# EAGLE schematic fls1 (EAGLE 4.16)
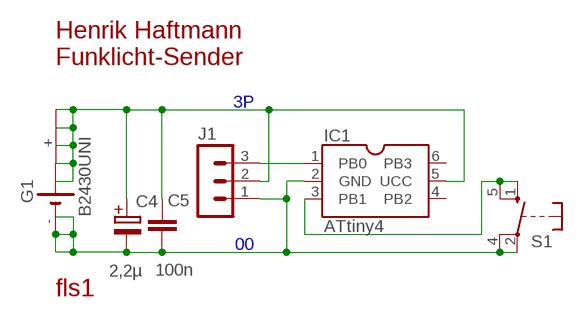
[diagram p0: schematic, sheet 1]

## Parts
C4  2,2µ  E01-5  [E01-5]
C5  100n  C0805  [0805]
G1  B2430UNI  [B2430UNI]
IC1  ATtiny4  ATTINY4  [SOT23-6]
J1  MA03-1  [MA03-1]
S1  TME1  [TME1]

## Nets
00: C4.- C5.2 G1.- G1.-@1(-) IC1.2(GND) J1.1 S1.2(P) S1.4(P)
3P: C4.+ C5.1 G1.+ G1.+@1(+) G1.+@2(+) G1.+@3(+) G1.+@4(+) IC1.5(UCC) J1.2
N$1: IC1.1(PB0) J1.3
N$2: IC1.3(PB1) S1.1(S) S1.5(S)
Unconnected: IC1.4(PB2) IC1.6(PB3)

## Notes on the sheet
- Henrik Haftmann
- Funklicht-Sender

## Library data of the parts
C4 = fu:E: Elektrolytkondensator, gepolt
C5 = fu:C: Kondensator
G1 = battery:B2430UNI: LI BATTERY
IC1 = fu:ATTINY4: AVR-Mikrocontroller TypFlashRAMADCSignatur ATtiny451232nein0x1E 0x8F 0x0A ATtiny551232ja0x1E 0x8F 0x09 ATtiny9102432nein0x1E 0x90 0x08 ATtiny10102432ja0x1E 0x90 0x03
J1 = con-lstb:MA03-1: PIN HEADER
S1 = switch-misc:TME1: SWITCH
